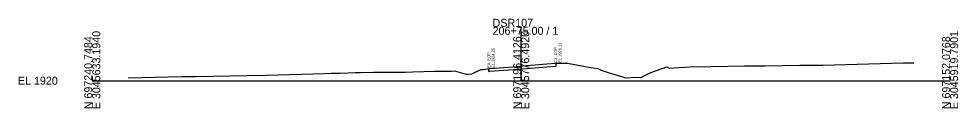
# Model space of a CAD drawing. Extents: x -26 to 19003, y -31 to 24541.
# Drawn here: x 1974.3 to 2302.8, y 14990.3 to 15021.8 of the extents above; entities that cross this region are included whole.
import ezdxf

# ---------------------------------------------------------------- set-up
doc = ezdxf.new("R2010")
doc.units = 0
for name, color, linetype in [('DESIGN - SHEET - Light Grid', 7, 'Continuous'), ('SURVEY - GROUND - Existing Pavement Layer', 7, 'Continuous'), ('SURVEY - GROUND - Existing Pavement Text', 7, 'Continuous'), ('SURVEY - GROUND - Top of Ground', 7, 'Continuous')]:
    doc.layers.add(name, color=color, linetype=linetype)

msp = doc.modelspace()

# ---------------------------------------------------------------- linework, layer by layer
at = {"layer": 'DESIGN - SHEET - Light Grid'}
for p, q in [((2150, 15000), (2150, 15018.94)), ((2000, 15000), (2150, 15000)), ((2150, 15000), (2300, 15000))]:
    msp.add_line(p, q, dxfattribs=at)
at = {"layer": 'SURVEY - GROUND - Existing Pavement Layer'}
for p, q in [((2138.69, 15003.25), (2138.69, 15004.25)), ((2147.17, 15003.92), (2150, 15004.15)), ((2150, 15004.15), (2150.43, 15004.19)), ((2150.43, 15004.19), (2159.01, 15004.87)), ((2159.01, 15004.87), (2162.08, 15005.11)), ((2162.08, 15006.11), (2162.08, 15005.11)), ((2138.69, 15003.25), (2139.08, 15003.3)), ((2139.08, 15003.3), (2147.17, 15003.92))]:
    msp.add_line(p, q, dxfattribs=at)
at = {"layer": 'SURVEY - GROUND - Top of Ground'}
msp.add_lwpolyline([(2012.58, 15001.04), (2031.49, 15001.43), (2036.22, 15001.47), (2054.01, 15001.84), (2061.02, 15001.96), (2081.17, 15002.54), (2083.56, 15002.62), (2084.12, 15002.63), (2086.7, 15002.68), (2091.92, 15002.83), (2093.85, 15002.83), (2098.36, 15002.94), (2103.4, 15003), (2109.43, 15002.99), (2112.11, 15003.11), (2119.73, 15003.33), (2122.56, 15003.37), (2125.67, 15003.37), (2126.64, 15003.41), (2130.82, 15002.26), (2131.7, 15002.33), (2132.8, 15002.43), (2135.86, 15003.88), (2136.82, 15003.98), (2137.45, 15004.09), (2138.1, 15004.16), (2138.69, 15004.25), (2139.08, 15004.3), (2147.17, 15004.92), (2150, 15005.15), (2150.43, 15005.19), (2159.01, 15005.87), (2162.08, 15006.11), (2163.11, 15006.19), (2164.06, 15006.21), (2166.15, 15006.15), (2174.39, 15004.64), (2176.8, 15004.23), (2177.94, 15003.71), (2180.82, 15002.71), (2183.58, 15001.93), (2186.43, 15001.02), (2190.06, 15001.22), (2191.82, 15001.11), (2195.39, 15002.84), (2200.93, 15004.83), (2201.7, 15004.45), (2208.85, 15004.86), (2216.28, 15005.01), (2228.15, 15005.2), (2235.22, 15005.25), (2247.46, 15005.51), (2255.46, 15005.49), (2283.6, 15006.22), (2287.33, 15006.31)], dxfattribs=at)

# ---------------------------------------------------------------- texts
at = {"layer": 'DESIGN - SHEET - Light Grid'}
for s, p in [('DSR107', (2140, 15018.94)), ('206+75.00 / 1', (2140, 15016.14)), ('EL 1920', (1974, 14998.6))]:
    msp.add_text(s, height=2.8, dxfattribs=at).set_placement(p)
for s, p in [('E 3045633.1940', (2002.8, 14990)), ('E 3045776.4920', (2152.8, 14990)), ('E 3045919.7901', (2302.8, 14990)), ('N 697240.7484', (2000, 14990)), ('N 697196.4126', (2150, 14990)), ('N 697152.0768', (2300, 14990))]:
    msp.add_text(s, height=2.8, rotation=90, dxfattribs=at).set_placement(p)
at = {"layer": 'SURVEY - GROUND - Existing Pavement Text'}
for s, p in [('EL.1924.25', (2140.69, 15004.45)), ('EX. EOP', (2162.58, 15006.31)), ('EL.1926.11', (2164.08, 15006.31)), ('EX. EOP', (2139.19, 15004.45))]:
    msp.add_text(s, height=1, rotation=90, dxfattribs=at).set_placement(p)

doc.saveas('drawing.dxf')
